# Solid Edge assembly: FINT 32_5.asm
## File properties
Title: Zylinder
Author: bmolnar
Template: iso assembly.asm
Last saved by: bmolnar
Revision: 6
Application: Solid Edge
Username: bmolnar
Dokumentum tartalom típus: 1
Document Number: FINT 32/5
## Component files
hrungsstange.par
Profilrohr.par
Platte.par
Kolbenstange.par
Kit_1.par
Kit_2.par
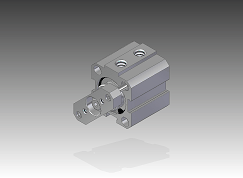
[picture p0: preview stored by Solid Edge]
